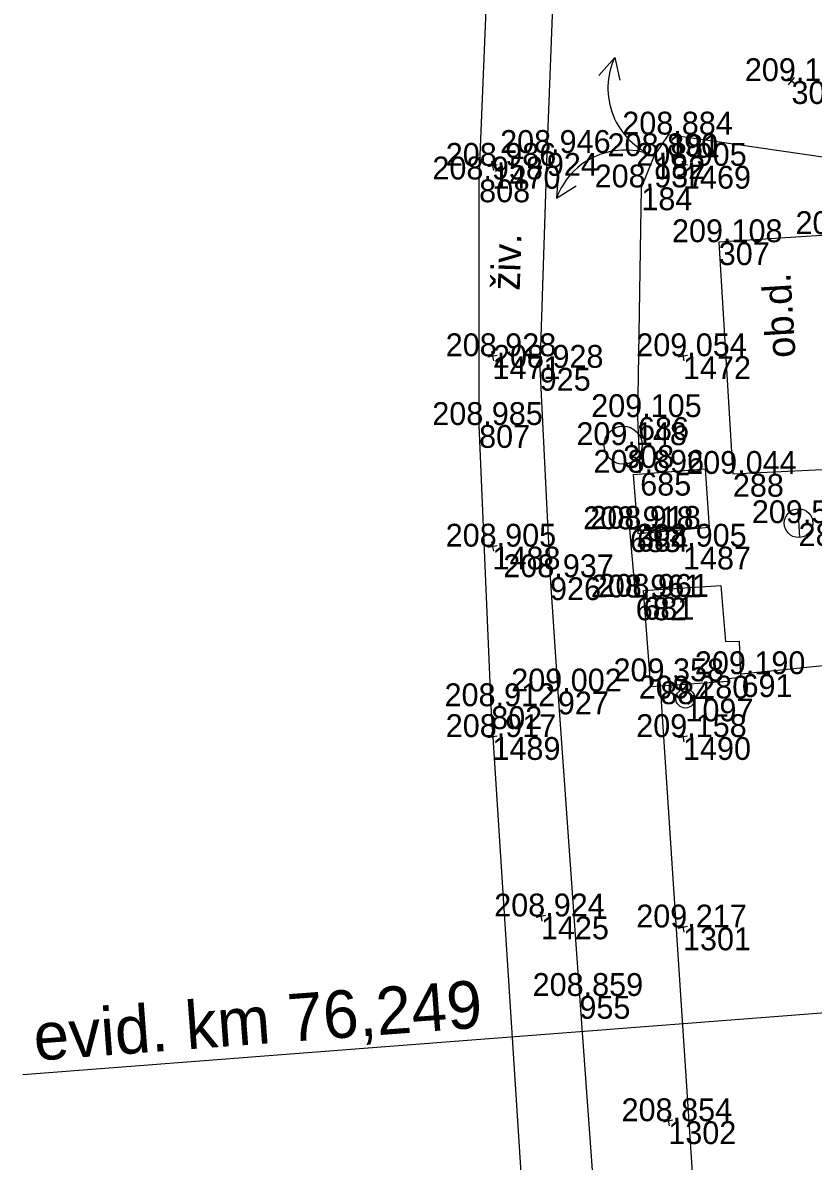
# Model space of a CAD drawing. Extents: x -556590 to -554855, y -1137918 to -1135717.
# Drawn here: x -555004.7 to -554963.2, y -1137502.3 to -1137442.5 of the extents above; entities that cross this region are included whole.
import ezdxf

# ---------------------------------------------------------------- set-up
doc = ezdxf.new("R2010")
doc.units = 0
for name, color, linetype in [('Vrstva 17', 7, 'Continuous'), ('Vrstva 23', 7, 'Continuous'), ('Vrstva 36', 7, 'Continuous'), ('Vrstva 41', 7, 'Continuous'), ('Vrstva 43', 7, 'Continuous'), ('Vrstva 49', 7, 'Continuous'), ('Vrstva 51', 7, 'Continuous'), ('Vrstva 6', 7, 'Continuous'), ('Vrstva 60', 7, 'Continuous'), ('Vrstva 61', 7, 'Continuous')]:
    doc.layers.add(name, color=color, linetype=linetype)

msp = doc.modelspace()

# ---------------------------------------------------------------- linework, layer by layer
at = {"layer": 'Vrstva 17'}
for points in [[(-554974.409, -1137445.262), (-554973.581, -1137444.306), (-554973.316, -1137445.498)], [(-554972.184, -1137451.132), (-554971.506, -1137449.493), (-554970.734, -1137448.358)], [(-554970.734, -1137448.358), (-554957.822, -1137450.233), (-554957.322, -1137452.614), (-554956.729, -1137467.849), (-554960.529, -1137468.043), (-554960.413, -1137476.033), (-554966.925, -1137476.698)], [(-554976.55, -1137450.437), (-554976.639, -1137451.698), (-554975.61, -1137451.042)], [(-554972.244, -1137466.119), (-554972.362, -1137463.196), (-554972.184, -1137451.132)], [(-554972.081, -1137472.637), (-554972.481, -1137472.667), (-554972.788, -1137469.088), (-554972.41, -1137469.065)], [(-554963.62, -1137596.043), (-554964.424, -1137584.011), (-554965.915, -1137560.578), (-554966.915, -1137543.736), (-554969.095, -1137508.973), (-554971.191, -1137477.072)]]:
    msp.add_lwpolyline(points, dxfattribs=at)
for centre, start, end in [((-554970.105, -1137445.924), 155.04158, 248.56146), ((-554973.035, -1137453.009), 66.49202, 160.01191)]:
    msp.add_arc(centre, 3.834, start, end, dxfattribs=at)
at = {"layer": 'Vrstva 23'}
for points in [[(-554967.381, -1137466.178), (-554960.869, -1137465.855), (-554961.639, -1137453.586), (-554968.122, -1137454.012), (-554967.381, -1137466.178)], [(-554968.83, -1137465.921), (-554968.624, -1137468.987), (-554972.357, -1137469.33), (-554972.589, -1137466.213), (-554968.83, -1137465.921)], [(-554968.007, -1137472.044), (-554967.776, -1137474.99), (-554967.057, -1137474.962), (-554966.987, -1137476.878), (-554967.617, -1137476.942), (-554967.61, -1137477.089), (-554971.693, -1137477.361), (-554972.069, -1137472.297), (-554968.007, -1137472.044)]]:
    msp.add_lwpolyline(points, dxfattribs=at)
at = {"layer": 'Vrstva 36'}
msp.add_circle((-554969.871, -1137477.976), 0.5, dxfattribs=at)
at = {"layer": 'Vrstva 41'}
msp.add_line((-554963.979, -1137468.016), (-554963.885, -1137469.518), dxfattribs=at)
msp.add_circle((-554963.932, -1137468.767), 0.752, dxfattribs=at)
at = {"layer": 'Vrstva 43'}
msp.add_circle((-554973.14, -1137464.669), 1, dxfattribs=at)
at = {"layer": 'Vrstva 49'}
for p, q in [((-554964.113, -1137445.715), (-554964.491, -1137445.389)), ((-554964.465, -1137445.741), (-554964.139, -1137445.363)), ((-554980.047, -1137449.754), (-554979.953, -1137450.246)), ((-554970.047, -1137449.754), (-554969.953, -1137450.246)), ((-554979.754, -1137449.953), (-554980.246, -1137450.047)), ((-554969.754, -1137449.953), (-554970.246, -1137450.047)), ((-554979.754, -1137459.953), (-554980.246, -1137460.047)), ((-554980.047, -1137459.754), (-554979.953, -1137460.246)), ((-554969.754, -1137459.953), (-554970.246, -1137460.047)), ((-554970.047, -1137459.754), (-554969.953, -1137460.246)), ((-554979.754, -1137469.953), (-554980.246, -1137470.047)), ((-554980.047, -1137469.754), (-554979.953, -1137470.246)), ((-554969.754, -1137469.953), (-554970.246, -1137470.047)), ((-554970.047, -1137469.754), (-554969.953, -1137470.246)), ((-554980.047, -1137479.754), (-554979.953, -1137480.246)), ((-554970.047, -1137479.754), (-554969.953, -1137480.246)), ((-554979.754, -1137479.953), (-554980.246, -1137480.047)), ((-554969.754, -1137479.953), (-554970.246, -1137480.047)), ((-554977.504, -1137489.177), (-554977.41, -1137489.669)), ((-554977.211, -1137489.376), (-554977.703, -1137489.47)), ((-554970.047, -1137489.754), (-554969.953, -1137490.246)), ((-554969.754, -1137489.953), (-554970.246, -1137490.047)), ((-554970.818, -1137499.931), (-554970.724, -1137500.423)), ((-554970.525, -1137500.13), (-554971.017, -1137500.224))]:
    msp.add_line(p, q, dxfattribs=at)
at = {"layer": 'Vrstva 51'}
for points in [[(-554976.695, -1137437.545), (-554977.147, -1137449.324), (-554977.521, -1137460.608), (-554976.979, -1137471.607), (-554976.567, -1137477.608), (-554975.438, -1137493.598), (-554973.245, -1137523.715), (-554970.78, -1137559.924)], [(-554976.027, -1137608.118), (-554973.798, -1137605.332), (-554972.683, -1137602.879), (-554972.003, -1137600.068), (-554972.088, -1137595.595), (-554973.123, -1137583.295), (-554974.615, -1137561.273), (-554975.973, -1137541.93), (-554977.781, -1137514.038), (-554980.067, -1137478.381), (-554980.702, -1137463.612), (-554980.699, -1137450.714), (-554980.221, -1137439.24)]]:
    msp.add_lwpolyline(points, dxfattribs=at)
at = {"layer": 'Vrstva 6'}
msp.add_line((-554945.217, -1137493.144), (-555004.655, -1137497.744), dxfattribs=at)
at = {"layer": 'Vrstva 60'}
for p, q in [((-554964.302, -1137445.552), (-554964.302, -1137445.552)), ((-554970.734, -1137448.358), (-554970.734, -1137448.358)), ((-554977.147, -1137449.324), (-554977.147, -1137449.324)), ((-554971.506, -1137449.493), (-554971.506, -1137449.493)), ((-554980, -1137450), (-554980, -1137450)), ((-554970, -1137450), (-554970, -1137450)), ((-554980.699, -1137450.714), (-554980.699, -1137450.714)), ((-554972.184, -1137451.132), (-554972.184, -1137451.132)), ((-554968.122, -1137454.012), (-554968.122, -1137454.012)), ((-554980, -1137460), (-554980, -1137460)), ((-554970, -1137460), (-554970, -1137460)), ((-554977.521, -1137460.608), (-554977.521, -1137460.608)), ((-554980.702, -1137463.612), (-554980.702, -1137463.612)), ((-554972.362, -1137463.196), (-554972.362, -1137463.196)), ((-554973.14, -1137464.669), (-554973.14, -1137464.669)), ((-554972.244, -1137466.119), (-554972.244, -1137466.119)), ((-554967.381, -1137466.178), (-554967.381, -1137466.178)), ((-554963.932, -1137468.767), (-554963.932, -1137468.767)), ((-554972.788, -1137469.088), (-554972.788, -1137469.088)), ((-554972.41, -1137469.065), (-554972.41, -1137469.065)), ((-554980, -1137470), (-554980, -1137470)), ((-554970, -1137470), (-554970, -1137470)), ((-554976.979, -1137471.607), (-554976.979, -1137471.607)), ((-554972.481, -1137472.667), (-554972.481, -1137472.667)), ((-554972.081, -1137472.637), (-554972.081, -1137472.637)), ((-554966.925, -1137476.698), (-554966.925, -1137476.698)), ((-554971.191, -1137477.072), (-554971.191, -1137477.072)), ((-554976.567, -1137477.608), (-554976.567, -1137477.608)), ((-554980.067, -1137478.381), (-554980.067, -1137478.381)), ((-554969.871, -1137477.976), (-554969.871, -1137477.976)), ((-554980, -1137480), (-554980, -1137480)), ((-554970, -1137480), (-554970, -1137480)), ((-554977.457, -1137489.423), (-554977.457, -1137489.423)), ((-554970, -1137490), (-554970, -1137490)), ((-554975.438, -1137493.598), (-554975.438, -1137493.598)), ((-554970.771, -1137500.177), (-554970.771, -1137500.177))]:
    msp.add_line(p, q, dxfattribs=at)

# ---------------------------------------------------------------- texts
at = {"layer": 'Vrstva 23'}
msp.add_text('ob.d.', height=1.5, rotation=93.59116, dxfattribs=at).set_placement((-554964.086, -1137460.045))
at = {"layer": 'Vrstva 51'}
msp.add_text('živ.', height=1.5, rotation=88.10167, dxfattribs=at).set_placement((-554978.571, -1137456.574))
at = {"layer": 'Vrstva 6'}
msp.add_text('evid. km 76,249', height=2.5, rotation=4.25916, dxfattribs=at).set_placement((-555004, -1137497))
at = {"layer": 'Vrstva 60'}
for s, p in [('306', (-554964.302, -1137446.752)), ('181', (-554970.734, -1137449.558)), ('924', (-554977.147, -1137450.524)), ('182', (-554971.506, -1137450.693)), ('1470', (-554980, -1137451.2)), ('1469', (-554970, -1137451.2)), ('808', (-554980.699, -1137451.914)), ('184', (-554972.184, -1137452.332)), ('307', (-554968.122, -1137455.212)), ('1471', (-554980, -1137461.2)), ('1472', (-554970, -1137461.2)), ('925', (-554977.521, -1137461.808)), ('807', (-554980.702, -1137464.812)), ('686', (-554972.362, -1137464.396)), ('308', (-554973.14, -1137465.869)), ('685', (-554972.244, -1137467.319)), ('288', (-554967.381, -1137467.378)), ('289', (-554963.932, -1137469.967)), ('683', (-554972.788, -1137470.288)), ('684', (-554972.41, -1137470.265)), ('1488', (-554980, -1137471.2)), ('1487', (-554970, -1137471.2)), ('926', (-554976.979, -1137472.807)), ('682', (-554972.481, -1137473.867)), ('681', (-554972.081, -1137473.837)), ('691', (-554966.925, -1137477.898)), ('884', (-554971.191, -1137478.272)), ('927', (-554976.567, -1137478.808)), ('1097', (-554969.871, -1137479.176)), ('802', (-554980.067, -1137479.581)), ('1489', (-554980, -1137481.2)), ('1490', (-554970, -1137481.2)), ('1425', (-554977.457, -1137490.623)), ('1301', (-554970, -1137491.2)), ('955', (-554975.438, -1137494.798)), ('1302', (-554970.771, -1137501.377))]:
    msp.add_text(s, height=1.2, dxfattribs=at).set_placement(p)
at = {"layer": 'Vrstva 61'}
for s, p in [('209.140', (-554966.753, -1137445.552)), ('208.884', (-554973.185, -1137448.358)), ('208.946', (-554979.599, -1137449.324)), ('208.890', (-554973.957, -1137449.493)), ('208.986', (-554982.452, -1137450)), ('208.905', (-554972.456, -1137450)), ('208.958', (-554983.153, -1137450.714)), ('208.937', (-554974.636, -1137451.132)), ('209.108', (-554970.576, -1137454.012)), ('209.003', (-554964.091, -1137453.586)), ('208.928', (-554982.454, -1137460)), ('209.054', (-554972.451, -1137460)), ('208.928', (-554979.975, -1137460.608)), ('208.985', (-554983.158, -1137463.612)), ('209.105', (-554974.818, -1137463.196)), ('209.148', (-554975.594, -1137464.669)), ('208.896', (-554974.696, -1137466.119)), ('209.044', (-554969.832, -1137466.178)), ('209.538', (-554966.386, -1137468.767)), ('208.918', (-554975.242, -1137469.088)), ('208.918', (-554974.864, -1137469.065)), ('208.905', (-554982.456, -1137470)), ('208.905', (-554972.456, -1137470)), ('208.937', (-554979.431, -1137471.607)), ('208.961', (-554974.838, -1137472.667)), ('208.961', (-554974.438, -1137472.637)), ('209.190', (-554969.376, -1137476.698)), ('209.358', (-554973.645, -1137477.072)), ('209.002', (-554979.015, -1137477.608)), ('209.280', (-554972.322, -1137477.976)), ('208.912', (-554982.515, -1137478.381)), ('208.917', (-554982.452, -1137480)), ('209.158', (-554972.454, -1137480)), ('208.924', (-554979.908, -1137489.423)), ('209.217', (-554972.452, -1137490)), ('208.859', (-554977.892, -1137493.598)), ('208.854', (-554973.222, -1137500.177))]:
    msp.add_text(s, height=1.2, dxfattribs=at).set_placement(p)

doc.saveas('drawing.dxf')
